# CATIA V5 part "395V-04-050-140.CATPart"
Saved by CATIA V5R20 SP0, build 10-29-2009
Part number: 395V-04-050-140
Source: Unknown
Property "A": "0.000"
Property "ARTICLENO": "395V-04-050-140"
Property "BOMINFO": "395V-04-050-140"
Property "CODE": "395V-04-050-140"
Property "D": "40.000"
Property "D1": "23.000"
Property "D2": "33.000"
Property "D3": "60.000"
Property "FORM": "A"
Property "L": "140.000"
Property "L1": "18.000"
Property "L2": "54.000"
Property "L3": "40.000"
Property "L4": "10.000"
Property "LINA": "395V-04-050-140"
Property "MAXLOAD": "3200 Kg"
Property "MDW": "6400 Kg"
Property "NB": "395V-04-050-140"
Property "NBSYN": "$CODE."
Property "NN": "395V"
Property "NT": "VDI 3366 Lifting Brackets"
Property "SUPPLIER": "CF"
Property "T": "21.500"
Property "W": "50.000"
Bounding box of the stored display mesh (mm): x -25 to 25, y 0 to 140, z -25 to 25
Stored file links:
  C:\Users\Utente\Desktop\3D files 395V\395V-04-050-140.CATPart
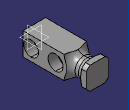
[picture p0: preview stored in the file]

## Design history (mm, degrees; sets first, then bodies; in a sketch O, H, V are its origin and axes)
Body1 "Geometry.1" (main body)
  Solid1 "395V-04-050-140.catpart": solid without history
